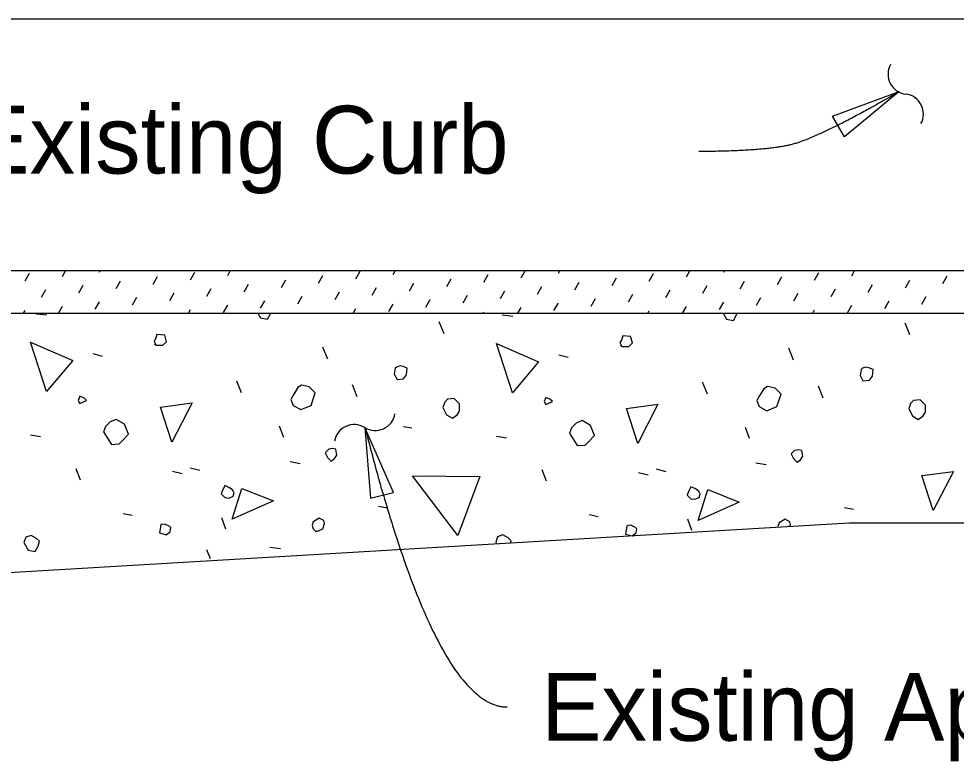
# Model space of a CAD drawing. Extents: x 21587 to 21659.1, y 56113.9 to 56155.9.
# Drawn here: x 21616.36 to 21619.146, y 56132.593 to 56134.801 of the extents above; entities that cross this region are included whole.
import ezdxf

# ---------------------------------------------------------------- set-up
doc = ezdxf.new("R2010")
doc.units = 0
for name, color, linetype in [('AdhocPoint_dp', 7, 'Continuous'), ('PlotBorder_dp', 7, 'Continuous'), ('SheetBorder_dp', 7, 'Continuous'), ('TextMisc', 7, 'Continuous')]:
    doc.layers.add(name, color=color, linetype=linetype)

msp = doc.modelspace()

# ---------------------------------------------------------------- linework, layer by layer
at = {"layer": 'AdhocPoint_dp'}
for p, q in [((21613.608, 56134.8009), (21621.5551, 56134.8009)), ((21624.3563, 56134.0511), (21613.608, 56134.0511)), ((21613.608, 56133.926), (21621.9231, 56133.926)), ((21618.8279, 56133.301), (21614.608, 56133.0509)), ((21624.3563, 56133.301), (21618.8279, 56133.301))]:
    msp.add_line(p, q, dxfattribs=at)
at = {"layer": 'PlotBorder_dp'}
for points in [[(21618.9767, 56134.5845), (21618.814, 56134.4497), (21618.7787, 56134.5108)], [(21617.3888, 56133.5857), (21617.4059, 56133.3752), (21617.4742, 56133.3926)]]:
    msp.add_lwpolyline(points, close=True, dxfattribs=at)
for centre, start, end in [((21619.0033, 56134.636), 151.5267, 263.2539), ((21618.9893, 56134.5176), 331.5267, 83.2539), ((21617.4197, 56133.6363), 238.4384, 350.1656), ((21617.3573, 56133.5347), 58.4384, 170.1656)]:
    msp.add_arc(centre, 0.0596, start, end, dxfattribs=at)
for points in [[(21618.3816, 56134.4071), (21618.5758, 56134.4079), (21618.7398, 56134.4476), (21618.9767, 56134.5845)], [(21617.3892, 56133.5857), (21617.6004, 56132.7545), (21617.8116, 56132.7545)]]:
    msp.add_open_spline(points, degree=2, dxfattribs=at)
at = {"layer": 'TextMisc'}
for p, q in [((21616.3793, 56134.0219), (21616.3922, 56134.0443)), ((21616.4899, 56134.0349), (21616.4993, 56134.0511)), ((21616.6005, 56134.0479), (21616.6024, 56134.0511)), ((21616.76, 56134.012), (21616.773, 56134.0344)), ((21616.8706, 56134.0249), (21616.8836, 56134.0473)), ((21616.9813, 56134.0379), (21616.9889, 56134.0511)), ((21617.0919, 56134.0509), (21617.092, 56134.0511)), ((21617.2514, 56134.015), (21617.2643, 56134.0374)), ((21617.362, 56134.028), (21617.375, 56134.0504)), ((21617.4726, 56134.0409), (21617.4785, 56134.0511)), ((21617.7427, 56134.018), (21617.7557, 56134.0404)), ((21617.8534, 56134.031), (21617.865, 56134.0511)), ((21617.964, 56134.044), (21617.9681, 56134.0511)), ((21618.2341, 56134.021), (21618.2471, 56134.0434)), ((21618.3447, 56134.034), (21618.3546, 56134.0511)), ((21618.4554, 56134.047), (21618.4578, 56134.0511)), ((21618.7255, 56134.0241), (21618.7384, 56134.0465)), ((21618.8361, 56134.037), (21618.8442, 56134.0511)), ((21618.9467, 56134.05), (21618.9474, 56134.0511)), ((21619.1062, 56134.0141), (21619.1192, 56134.0365)), ((21616.5387, 56133.9861), (21616.5517, 56134.0084)), ((21616.6494, 56133.999), (21616.6623, 56134.0214)), ((21617.0301, 56133.9891), (21617.0431, 56134.0115)), ((21617.1407, 56134.002), (21617.1537, 56134.0244)), ((21617.5215, 56133.9921), (21617.5344, 56134.0145)), ((21617.6321, 56134.0051), (21617.6451, 56134.0275)), ((21618.0128, 56133.9951), (21618.0258, 56134.0175)), ((21618.1235, 56134.0081), (21618.1364, 56134.0305)), ((21618.3936, 56133.9852), (21618.4065, 56134.0076)), ((21618.5042, 56133.9981), (21618.5172, 56134.0205)), ((21618.6148, 56134.0111), (21618.6278, 56134.0335)), ((21618.8849, 56133.9882), (21618.8979, 56134.0106)), ((21618.9956, 56134.0012), (21619.0085, 56134.0235)), ((21616.4281, 56133.9731), (21616.4411, 56133.9955)), ((21616.8088, 56133.9631), (21616.8218, 56133.9855)), ((21616.9195, 56133.9761), (21616.9324, 56133.9985)), ((21617.3002, 56133.9662), (21617.3132, 56133.9886)), ((21617.4108, 56133.9791), (21617.4238, 56134.0015)), ((21617.6809, 56133.9562), (21617.6939, 56133.9786)), ((21617.7916, 56133.9692), (21617.8045, 56133.9916)), ((21617.9022, 56133.9822), (21617.9152, 56134.0045)), ((21618.1723, 56133.9592), (21618.1853, 56133.9816)), ((21618.2829, 56133.9722), (21618.2959, 56133.9946)), ((21618.6637, 56133.9623), (21618.6766, 56133.9847)), ((21618.7743, 56133.9752), (21618.7873, 56133.9976)), ((21616.5876, 56133.9372), (21616.6005, 56133.9596)), ((21616.6982, 56133.9502), (21616.7112, 56133.9726)), ((21617.0789, 56133.9402), (21617.0919, 56133.9626)), ((21617.1896, 56133.9532), (21617.2025, 56133.9756)), ((21617.4597, 56133.9303), (21617.4726, 56133.9527)), ((21617.5703, 56133.9433), (21617.5833, 56133.9657)), ((21617.951, 56133.9333), (21617.964, 56133.9557)), ((21618.0617, 56133.9463), (21618.0746, 56133.9687)), ((21618.4424, 56133.9363), (21618.4554, 56133.9587)), ((21618.553, 56133.9493), (21618.566, 56133.9717)), ((21618.9338, 56133.9394), (21618.9467, 56133.9617)), ((21619.0444, 56133.9523), (21619.0574, 56133.9747)), ((21616.3748, 56133.926), (21616.3793, 56133.9337)), ((21616.4123, 56133.9236), (21616.4441, 56133.9201)), ((21616.478, 56133.926), (21616.4899, 56133.9466)), ((21616.8645, 56133.926), (21616.8706, 56133.9367)), ((21616.9683, 56133.9273), (21616.9813, 56133.9497)), ((21617.2509, 56133.926), (21617.2514, 56133.9268)), ((21617.3541, 56133.926), (21617.362, 56133.9397)), ((21617.7406, 56133.926), (21617.7427, 56133.9298)), ((21617.8437, 56133.926), (21617.8534, 56133.9427)), ((21618.2302, 56133.926), (21618.2341, 56133.9328)), ((21618.3333, 56133.926), (21618.3447, 56133.9458)), ((21618.7198, 56133.926), (21618.7255, 56133.9358)), ((21618.8231, 56133.9264), (21618.8361, 56133.9488)), ((21617.6243, 56133.8641), (21617.6102, 56133.8995)), ((21617.7969, 56133.9201), (21617.8288, 56133.9165)), ((21619.009, 56133.8606), (21618.9949, 56133.8959)), ((21617.2785, 56133.7892), (21617.2643, 56133.8246)), ((21618.6631, 56133.7857), (21618.649, 56133.8211)), ((21616.5802, 56133.8051), (21616.6085, 56133.7981)), ((21617.9649, 56133.8016), (21617.9932, 56133.7945)), ((21617.0221, 56133.6885), (21617.008, 56133.7238)), ((21617.3662, 56133.6767), (21617.3521, 56133.7121)), ((21618.4068, 56133.6849), (21618.3927, 56133.7203)), ((21618.7509, 56133.6732), (21618.7368, 56133.7085)), ((21617.1477, 56133.5559), (21617.1353, 56133.5895)), ((21617.5041, 56133.5883), (21617.5289, 56133.5848)), ((21616.3952, 56133.5636), (21616.4253, 56133.5583)), ((21618.5323, 56133.5524), (21618.52, 56133.5859)), ((21617.7799, 56133.5601), (21617.8099, 56133.5547)), ((21617.1665, 56133.484), (21617.1965, 56133.4787)), ((21618.5512, 56133.4805), (21618.5812, 56133.4752)), ((21616.5437, 56133.4292), (21616.5313, 56133.4628)), ((21616.8177, 56133.4558), (21616.846, 56133.4487)), ((21616.8701, 56133.4657), (21616.8984, 56133.4587)), ((21617.9284, 56133.4257), (21617.916, 56133.4593)), ((21618.2024, 56133.4522), (21618.2307, 56133.4451)), ((21618.2548, 56133.4622), (21618.2831, 56133.4551)), ((21617.4299, 56133.3515), (21617.4564, 56133.3462)), ((21618.8145, 56133.3479), (21618.8411, 56133.3426)), ((21616.671, 56133.3302), (21616.6975, 56133.3249)), ((21616.9762, 56133.2831), (21616.9638, 56133.3167)), ((21618.0557, 56133.3267), (21618.0822, 56133.3214)), ((21618.3609, 56133.2796), (21618.3485, 56133.3132)), ((21617.1064, 56133.2295), (21617.1382, 56133.2259)), ((21616.9302, 56133.1952), (21616.9196, 56133.2217))]:
    msp.add_line(p, q, dxfattribs=at)
for points in [[(21617.0705, 56133.926), (21617.0787, 56133.9112), (21617.0999, 56133.9077), (21617.1088, 56133.9236), (21617.1094, 56133.926)], [(21618.4533, 56133.926), (21618.4545, 56133.9236)], [(21618.4545, 56133.9236), (21618.4634, 56133.9077), (21618.4846, 56133.9041), (21618.4934, 56133.9201), (21618.4949, 56133.926)], [(21616.4429, 56133.6926), (21616.3952, 56133.8394), (21616.5207, 56133.7846), (21616.4429, 56133.6926)], [(21616.7676, 56133.8299), (21616.7888, 56133.8299), (21616.7994, 56133.8405), (21616.7941, 56133.8599), (21616.7711, 56133.8617), (21616.7676, 56133.8511), (21616.7623, 56133.8423), (21616.7676, 56133.8299), (21616.764, 56133.8334)], [(21618.1523, 56133.8264), (21618.1735, 56133.8264), (21618.1841, 56133.837), (21618.1788, 56133.8564), (21618.1558, 56133.8582), (21618.1523, 56133.8476), (21618.147, 56133.8387), (21618.1523, 56133.8264), (21618.1487, 56133.8299)], [(21617.8276, 56133.6891), (21617.7799, 56133.8358), (21617.9054, 56133.781), (21617.8276, 56133.6891)], [(21617.4758, 56133.7439), (21617.4847, 56133.728), (21617.5041, 56133.7298), (21617.513, 56133.7421), (21617.5147, 56133.7616), (21617.5023, 56133.7669), (21617.4935, 56133.7686), (21617.4829, 56133.7651), (21617.4794, 56133.7616), (21617.4758, 56133.7439)], [(21618.8605, 56133.7404), (21618.8693, 56133.7245), (21618.8888, 56133.7262), (21618.8976, 56133.7386), (21618.8994, 56133.758), (21618.887, 56133.7633), (21618.8782, 56133.7651), (21618.8676, 56133.7616), (21618.864, 56133.758), (21618.8605, 56133.7404)], [(21617.1759, 56133.6514), (21617.1989, 56133.639), (21617.229, 56133.6514), (21617.2413, 56133.6885), (21617.2237, 56133.7062), (21617.2007, 56133.7115), (21617.1901, 56133.7044), (21617.1777, 56133.6849), (21617.1689, 56133.669), (21617.1759, 56133.6514)], [(21618.5606, 56133.6478), (21618.5836, 56133.6354), (21618.6136, 56133.6478), (21618.626, 56133.6849), (21618.6083, 56133.7026), (21618.5854, 56133.7079), (21618.5748, 56133.7008), (21618.5624, 56133.6814), (21618.5535, 56133.6655), (21618.5606, 56133.6478)], [(21616.5419, 56133.6573), (21616.5614, 56133.6661), (21616.5543, 56133.6732), (21616.5419, 56133.6785), (21616.5366, 56133.6661), (21616.5419, 56133.6573)], [(21617.9266, 56133.6537), (21617.9461, 56133.6626), (21617.939, 56133.6697), (21617.9266, 56133.675), (21617.9213, 56133.6626), (21617.9266, 56133.6537)], [(21616.8153, 56133.5417), (21616.7817, 56133.646), (21616.8754, 56133.6584), (21616.8153, 56133.5417)], [(21617.6208, 56133.6449), (21617.6314, 56133.6237), (21617.6491, 56133.6131), (21617.6632, 56133.6237), (21617.6703, 56133.6343), (21617.6703, 56133.6555), (21617.6544, 56133.6714), (21617.6349, 56133.6697), (21617.6261, 56133.6608), (21617.6208, 56133.6449)], [(21618.2, 56133.5382), (21618.1664, 56133.6425), (21618.2601, 56133.6549), (21618.2, 56133.5382)], [(21619.0055, 56133.6414), (21619.0161, 56133.6202), (21619.0338, 56133.6096), (21619.0479, 56133.6202), (21619.055, 56133.6308), (21619.055, 56133.652), (21619.0391, 56133.6679), (21619.0196, 56133.6661), (21619.0108, 56133.6573), (21619.0055, 56133.6414)], [(21616.6126, 56133.5724), (21616.6356, 56133.5353), (21616.6586, 56133.5371), (21616.6674, 56133.5459), (21616.6869, 56133.5654), (21616.6745, 56133.5954), (21616.6498, 56133.6096), (21616.6321, 56133.6025), (21616.6179, 56133.5883), (21616.6126, 56133.5724)], [(21617.9973, 56133.5689), (21618.0203, 56133.5318), (21618.0433, 56133.5335), (21618.0521, 56133.5424), (21618.0716, 56133.5618), (21618.0592, 56133.5919), (21618.0344, 56133.606), (21618.0168, 56133.5989), (21618.0026, 56133.5848), (21617.9973, 56133.5689)], [(21617.2778, 56133.4964), (21617.2884, 56133.4858), (21617.2991, 56133.4929), (21617.3061, 56133.5035), (21617.3026, 56133.5212), (21617.2938, 56133.5229), (21617.2814, 56133.5212), (21617.2708, 56133.5106), (21617.2778, 56133.4964)], [(21618.6625, 56133.4929), (21618.6731, 56133.4823), (21618.6837, 56133.4893), (21618.6908, 56133.4999), (21618.6873, 56133.5176), (21618.6784, 56133.5194), (21618.6661, 56133.5176), (21618.6554, 56133.507), (21618.6625, 56133.4929)], [(21619.0778, 56133.3385), (21619.0443, 56133.4428), (21619.1379, 56133.4551), (21619.0778, 56133.3385)], [(21617.665, 56133.2648), (21617.5306, 56133.4416), (21617.7304, 56133.4398), (21617.665, 56133.2648)], [(21616.9726, 56133.3773), (21616.985, 56133.3756), (21616.9974, 56133.3809), (21617.0009, 56133.3915), (21616.9956, 56133.4003), (21616.985, 56133.4074), (21616.9726, 56133.4127), (21616.9656, 56133.3986), (21616.962, 56133.388), (21616.9726, 56133.3773)], [(21616.995, 56133.3126), (21617.0233, 56133.4045), (21617.117, 56133.3674), (21616.995, 56133.3126)], [(21618.3573, 56133.3738), (21618.3697, 56133.372), (21618.3821, 56133.3773), (21618.3856, 56133.388), (21618.3803, 56133.3968), (21618.3697, 56133.4039), (21618.3573, 56133.4092), (21618.3503, 56133.395), (21618.3467, 56133.3844), (21618.3573, 56133.3738)], [(21618.3797, 56133.309), (21618.408, 56133.401), (21618.5017, 56133.3638), (21618.3797, 56133.309)], [(21617.2425, 56133.2772), (21617.2496, 56133.2772), (21617.2637, 56133.2843), (21617.269, 56133.3002), (21617.2672, 56133.309), (21617.2531, 56133.3161), (21617.2354, 56133.3055), (21617.2319, 56133.2949), (21617.2354, 56133.2843), (21617.2425, 56133.2772)], [(21618.6514, 56133.2899), (21618.6537, 56133.2967), (21618.6519, 56133.3055), (21618.6378, 56133.3126), (21618.6201, 56133.302), (21618.6166, 56133.2914), (21618.6177, 56133.2878)], [(21616.7788, 56133.2719), (21616.7983, 56133.2666), (21616.8106, 56133.2754), (21616.8124, 56133.2878), (21616.8089, 56133.2914), (21616.7947, 56133.2984), (21616.7824, 56133.2967), (21616.7806, 56133.2843), (21616.7788, 56133.2719)], [(21618.1635, 56133.2684), (21618.1829, 56133.2631), (21618.1953, 56133.2719), (21618.1971, 56133.2843), (21618.1935, 56133.2878), (21618.1794, 56133.2949), (21618.167, 56133.2931), (21618.1653, 56133.2807), (21618.1635, 56133.2684)], [(21616.3793, 56133.2366), (21616.3881, 56133.2206), (21616.4094, 56133.2171), (21616.4182, 56133.233), (21616.4217, 56133.2472), (21616.4129, 56133.256), (21616.397, 56133.2648), (21616.3811, 56133.2595), (21616.3758, 56133.2436), (21616.3793, 56133.2366)], [(21617.8221, 56133.2418), (21617.8237, 56133.2484), (21617.8149, 56133.2572), (21617.799, 56133.2661), (21617.7831, 56133.2608), (21617.7778, 56133.2449), (21617.7806, 56133.2392)]]:
    msp.add_lwpolyline(points, dxfattribs=at)

# ---------------------------------------------------------------- texts
at = {"layer": 'SheetBorder_dp'}
for s, p in [('Existing Curb', (21616.213, 56134.3406)), ('Existing Approach Slab', (21617.9127, 56132.654))]:
    msp.add_text(s, height=0.2016, dxfattribs=at).set_placement(p)

doc.saveas('drawing.dxf')
